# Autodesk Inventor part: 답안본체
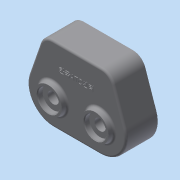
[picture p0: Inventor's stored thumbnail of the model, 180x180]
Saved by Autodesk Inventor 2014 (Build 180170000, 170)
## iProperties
Created: 2014-12
Part Number: 답안본체
Material: 일반
Document SubType Name: Modeling
Designer: user
Density: 1 g/cm^3
Appearance: 기본값
Author: user
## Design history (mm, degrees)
sketch "스케치1"
  geometry: L1 (-47, 0)-(47, 0); L2 (47, 0)-(66.565, -56.803); L3 (-47, 0)-(-66.565, -56.803); L4 (-32.527, -104.527)-(32.527, -104.527); L5 (-32.527, -68.527)-(0, -36); L6 (0, -36)-(32.527, -68.527); L7 (0, -36)-(0, -104.527); C1 r 24 at (0, -36); C2 r 24 at (-32.527, -68.527); C3 r 24 at (32.527, -68.527); A1 r 36 centre (32.527, -68.527) between (32.527, -104.527) and (66.565, -56.803); A2 r 36 centre (-32.527, -68.527) between (-66.565, -56.803) and (-32.527, -104.527); A3 r 46 centre (0, -36) between (32.527, -68.527) and (-32.527, -68.527); 2 further points
  constraints: 14 end point, 6 centre point, 6 point on circle, 5 coincident, 4 tangent, 2 midpoint, 1 horizontal, 1 horizontal alignment, 1 parallel, 1 perpendicular, 1 vertical alignment
  dimensions: "d0" = 36 radius of A2; "d1" = 94 distance of L1.start L1.end; "d2" = 36 distance from line of L6.end L4; "d5" = 92 diameter of A3; "d6" = 90 deg angle of L5 L6; "d7" = 48 diameter of C2; "d8" = 48 diameter of C3; "d9" = 48 diameter of C1; "d10" = 36 distance from line of L5.end L1
extrude "돌출1" new body sketch "스케치1" distance "d11" = 10; taper "d12" = 0 deg
node "작업 평면1"
sketch "스케치2"
  geometry: L1 (11.723, 10)-(-36, 10) reference; L2 (-20, 10)-(-18.766, 17); L3 (-18.766, 17)-(18.766, 17); L4 (68.527, 10)-(11.723, 10) reference; L5 (18.766, 17)-(20, 10); L6 (0, 0)-(0, 22.754); L7 (-36, 0)-(-36, 10) reference; L8 (0, 17)-(0, 10); L9 (0, 10)-(20, 10); 1 further point
  constraints: 12 end point, 5 point on line, 1 collinear, 1 midpoint, 1 parallel, 1 perpendicular
  dimensions: "d13" = 100 deg angle of L1 L2; "d14" = 100 deg angle of L4 L5; "d15" = 40 distance of L2.start L5.end; "d16" = 7 distance between parallel lines of L1 L3; "d17" = 36 distance between parallel lines of L7 L6
revolve "회전1" sketch "스케치2" stored, may be unused: angle "d18" = 90 deg
extrude "돌출2" join sketch "스케치1" distance "d19" = 34; taper "d20" = 0 deg
sketch "스케치3"
  geometry: C1 r 18.766 at (0, 0) reference; C2 r 18.766 at (-65.054, 0) reference; 3 further points
  constraints: 2 coincident
hole "구멍1" sketch "스케치3" at (0, 0), (-65.054, 0) diameter "d21" = 15.5; stored, may be unused: countersink angle "d25" = 90 deg, drill point angle "d27" = 0 deg; dims "d22" = 6, "d23" = 30, "d24" = 7, "d26" = 17
sketch "스케치4"
  geometry: L1 (66.565, -56.803)-(47, 0) reference; L2 (47, 0)-(-47, 0) reference; L3 (-47, 0)-(-66.565, -56.803) reference; L4 (-32.527, -104.527)-(32.527, -104.527) reference; L5 (-43.434, -5)-(43.434, -5); L6 (43.434, -5)-(61.837, -58.432); L7 (32.527, -99.527)-(-32.527, -99.527); L8 (-61.837, -58.432)-(-43.434, -5); A1 r 36 centre (-32.527, -68.527) between (-66.565, -56.803) and (-32.527, -104.527) reference; A2 r 36 centre (32.527, -68.527) between (32.527, -104.527) and (66.565, -56.803) reference; A3 r 31 centre (32.527, -68.527) between (32.527, -99.527) and (61.837, -58.432); A4 r 31 centre (-32.527, -68.527) between (-61.837, -58.432) and (-32.527, -99.527); 1 further point
  constraints: 8 end point, 4 point on circle, 2 centre point, 5 other
  dimensions: "d28" = 5 distance between parallel lines of L2 L5
extrude "돌출3" cut sketch "스케치4" distance "d29" = 23; taper "d30" = 0 deg
fillet "모깎기1" dims "d31" = 18
fillet "모깎기2" dims "d32" = 18
sketch "스케치5"
  geometry: L1 (-30.596, -5)-(30.596, -5) reference; L2 (-61.837, -58.432)-(-47.615, -17.138) reference; L3 (32.527, -99.527)-(-32.527, -99.527) reference; L4 (47.615, -17.138)-(61.837, -58.432) reference; A1 r 18 centre (30.596, -23) between (47.615, -17.138) and (30.596, -5) reference; A2 r 18 centre (-30.596, -23) between (-30.596, -5) and (-47.615, -17.138) reference; A3 r 31 centre (-32.527, -68.527) between (-61.837, -58.432) and (-32.527, -99.527) reference; A4 r 31 centre (32.527, -68.527) between (32.527, -99.527) and (61.837, -58.432) reference; 3 further points
  constraints: 2 coincident
hole "구멍2" sketch "스케치5" at (32.527, -68.527), (-32.527, -68.527) diameter "d33" = 35; stored, may be unused: countersink angle "d37" = 90 deg, drill point angle "d39" = 0 deg; dims "d34" = 6, "d35" = 30, "d36" = 7, "d38" = 11
sketch "스케치6"
  geometry: L1 (-30.596, -5)-(30.596, -5) reference; L2 (-61.837, -58.432)-(-47.615, -17.138) reference; L3 (32.527, -99.527)-(-32.527, -99.527) reference; L4 (47.615, -17.138)-(61.837, -58.432) reference; L5 (34.162, 0)-(-34.162, 0) reference; C1 r 17.5 at (32.527, -68.527) reference; C2 r 17.5 at (-32.527, -68.527) reference; A1 r 18 centre (30.596, -23) between (47.615, -17.138) and (30.596, -5) reference; A2 r 18 centre (-30.596, -23) between (-30.596, -5) and (-47.615, -17.138) reference; A3 r 31 centre (-32.527, -68.527) between (-61.837, -58.432) and (-32.527, -99.527) reference; A4 r 31 centre (32.527, -68.527) between (32.527, -99.527) and (61.837, -58.432) reference; A5 r 24 centre (-32.527, -68.527) between (-21.111, -47.416) and (-11.416, -57.111); A6 r 24 centre (32.527, -68.527) between (11.416, -57.111) and (21.111, -47.416); A7 r 24 centre (0, -36) between (21.111, -47.416) and (-21.111, -47.416); A8 r 24 centre (0, -36) between (-11.416, -57.111) and (11.416, -57.111); 2 further points
  constraints: 8 point on circle, 4 centre point, 2 coincident, 1 equal radius, 1 midpoint, 1 vertical alignment
  dimensions: "d40" = 48 diameter of A5; "d42" = 36 distance from line of A7.centre L5; "d43" = 24 radius of A7; "d44" = 24 radius of A8
extrude "돌출4" cut sketch "스케치6" distance "d45" = 11; taper "d46" = 0 deg
sketch "스케치7"
  geometry: C1 r 17.5 at (32.527, -68.527) reference; C2 r 17.5 at (-32.527, -68.527) reference; A1 r 24 centre (0, -36) between (21.111, -47.416) and (-21.111, -47.416) reference; A2 r 24 centre (-32.527, -68.527) between (-21.111, -47.416) and (-11.416, -57.111) reference; A3 r 24 centre (0, -36) between (-11.416, -57.111) and (11.416, -57.111) reference; A4 r 24 centre (32.527, -68.527) between (11.416, -57.111) and (21.111, -47.416) reference; 2 further points
  constraints: 1 coincident
hole "구멍3" sketch "스케치7" at (0, -36) diameter "d47" = 20; stored, may be unused: countersink angle "d51" = 90 deg, drill point angle "d53" = 0 deg; dims "d48" = 6, "d49" = 40, "d50" = 12, "d52" = 15
sketch "스케치8"
  geometry: L1 (-61.837, -58.432)-(-47.615, -17.138) reference; L2 (-30.596, -5)-(30.596, -5) reference; L3 (47.615, -17.138)-(61.837, -58.432) reference; L4 (32.527, -99.527)-(-32.527, -99.527) reference; L5 (-51.181, -12.138)-(-66.565, -56.803) reference; L6 (-32.527, -104.527)-(32.527, -104.527) reference; L7 (66.565, -56.803)-(51.181, -12.138) reference; L8 (34.162, 0)-(-34.162, 0) reference; L9 (47.615, -17.138)-(61.837, -58.432) reference; A1 r 18 centre (-30.596, -23) between (-30.596, -5) and (-47.615, -17.138) reference; A2 r 18 centre (30.596, -23) between (47.615, -17.138) and (30.596, -5) reference; A3 r 31 centre (32.527, -68.527) between (32.527, -99.527) and (61.837, -58.432) reference; A4 r 31 centre (-32.527, -68.527) between (-61.837, -58.432) and (-32.527, -99.527) reference; A5 r 18 centre (-34.162, -18) between (-34.162, 0) and (-51.181, -12.138) reference; A6 r 36 centre (-32.527, -68.527) between (-66.565, -56.803) and (-32.527, -104.527) reference; A7 r 36 centre (32.527, -68.527) between (32.527, -104.527) and (66.565, -56.803) reference; A8 r 18 centre (34.162, -18) between (51.181, -12.138) and (34.162, 0) reference; A9 r 8 centre (51.7, -29) between (49.095, -21.436) and (54.305, -36.564); 1 further point
  constraints: 3 point on line, 2 point on circle, 1 centre point
  dimensions: "d55" = 8 radius of A9; "d95" = 29 distance from line of A9.centre L8
extrude "돌출5" join sketch "스케치8" stored distance "d56" = 11; taper "d57" = 0 deg
sketch "스케치9"
  geometry: L1 (-51.181, -12.138)-(-66.565, -56.803) reference; L2 (-32.527, -104.527)-(32.527, -104.527) reference; L3 (66.565, -56.803)-(51.181, -12.138) reference; L4 (34.162, 0)-(-34.162, 0) reference; L5 (54.305, -36.564)-(61.837, -58.432) reference; L6 (32.527, -99.527)-(-32.527, -99.527) reference; L7 (-61.837, -58.432)-(-54.305, -36.564) reference; L8 (-49.095, -21.436)-(-47.615, -17.138) reference; L9 (-30.596, -5)-(30.596, -5) reference; L10 (47.615, -17.138)-(49.095, -21.436) reference; L11 (32.527, -99.527)-(-32.527, -99.527) reference; A1 r 18 centre (-34.162, -18) between (-34.162, 0) and (-51.181, -12.138) reference; A2 r 36 centre (-32.527, -68.527) between (-66.565, -56.803) and (-32.527, -104.527) reference; A3 r 36 centre (32.527, -68.527) between (32.527, -104.527) and (66.565, -56.803) reference; A4 r 18 centre (34.162, -18) between (51.181, -12.138) and (34.162, 0) reference; A5 r 8 centre (51.7, -29) between (49.095, -21.436) and (54.305, -36.564) reference; A6 r 31 centre (32.527, -68.527) between (32.527, -99.527) and (61.837, -58.432) reference; A7 r 31 centre (-32.527, -68.527) between (-61.837, -58.432) and (-32.527, -99.527) reference; A8 r 8 centre (-51.7, -29) between (-54.305, -36.564) and (-49.095, -21.436) reference; A9 r 18 centre (-30.596, -23) between (-30.596, -5) and (-47.615, -17.138) reference; A10 r 18 centre (30.596, -23) between (47.615, -17.138) and (30.596, -5) reference; A11 r 8 centre (0, -99.527) between (8, -99.527) and (-8, -99.527); 3 further points
  constraints: 3 point on circle, 2 midpoint, 2 point on line, 1 centre point, 1 vertical alignment
  dimensions: "d58" = 8 radius of A11
extrude "돌출6" join sketch "스케치9" stored distance "d59" = 11; taper "d60" = 0 deg
sketch "스케치10"
  geometry: L1 (-51.181, -12.138)-(-66.565, -56.803) reference; L2 (-32.527, -104.527)-(32.527, -104.527) reference; L3 (66.565, -56.803)-(51.181, -12.138) reference; L4 (34.162, 0)-(-34.162, 0) reference; L5 (-8, -99.527)-(-32.527, -99.527) reference; L6 (-61.837, -58.432)-(-54.305, -36.564) reference; L7 (-49.095, -21.436)-(-47.615, -17.138) reference; L8 (-30.596, -5)-(30.596, -5) reference; L9 (47.615, -17.138)-(49.095, -21.436) reference; L10 (54.305, -36.564)-(61.837, -58.432) reference; L11 (32.527, -99.527)-(8, -99.527) reference; A1 r 18 centre (-34.162, -18) between (-34.162, 0) and (-51.181, -12.138) reference; A2 r 36 centre (-32.527, -68.527) between (-66.565, -56.803) and (-32.527, -104.527) reference; A3 r 36 centre (32.527, -68.527) between (32.527, -104.527) and (66.565, -56.803) reference; A4 r 18 centre (34.162, -18) between (51.181, -12.138) and (34.162, 0) reference; A5 r 8 centre (0, -99.527) between (8, -99.527) and (-8, -99.527) reference; A6 r 31 centre (-32.527, -68.527) between (-61.837, -58.432) and (-32.527, -99.527) reference; A7 r 8 centre (-51.7, -29) between (-54.305, -36.564) and (-49.095, -21.436) reference; A8 r 18 centre (-30.596, -23) between (-30.596, -5) and (-47.615, -17.138) reference; A9 r 18 centre (30.596, -23) between (47.615, -17.138) and (30.596, -5) reference; A10 r 8 centre (51.7, -29) between (49.095, -21.436) and (54.305, -36.564) reference; A11 r 31 centre (32.527, -68.527) between (32.527, -99.527) and (61.837, -58.432) reference; 4 further points
  constraints: 3 coincident
hole "구멍4" sketch "스케치10" at (-51.7, -29), (51.7, -29), (0, -99.527) diameter "d61" = 4.134; stored, may be unused: countersink angle "d65" = 90 deg, drill point angle "d67" = 118 deg; dims "d62" = 20, "d63" = 40, "d64" = 12, "d66" = 23
fillet "모깎기3" dims "d68" = 3
fillet "모깎기4" dims "d69" = 3
fillet "모깎기5" dims "d70" = 3
fillet "모깎기6" dims "d71" = 3
fillet "모깎기7" dims "d72" = 3
fillet "모깎기8" dims "d73" = 0.3
fillet "모깎기9" dims "d74" = 3
fillet "모깎기10" dims "d75" = 0.3
fillet "모깎기11" dims "d76" = 0.1
chamfer "모따기1" distance "d77" = 1; stored, may be unused: second distance "d78" = 2, angle "d79" = 45 deg
chamfer "모따기2" distance "d80" = 1; stored, may be unused: second distance "d81" = 2, angle "d82" = 45 deg
chamfer "모따기3" distance "d83" = 1; stored, may be unused: second distance "d84" = 2, angle "d85" = 45 deg
chamfer "모따기4" distance "d86" = 1; stored, may be unused: second distance "d87" = 2, angle "d88" = 45 deg
chamfer "모따기5" distance "d89" = 1; stored, may be unused: second distance "d90" = 2, angle "d91" = 45 deg
sketch "스케치11"
  geometry: 2 further points
  constraints: 1 vertical alignment, 1 other
  dimensions: "d92" = 30 distance of point (0, -30) point (0, 0)
feature "엠보싱1" sketch "스케치11" dims "d0" = 36, "d1" = 94, "d2" = 36, "d5" = 92, "d6" = 90 deg, "d7" = 48, "d8" = 48, "d9" = 48, "d10" = 36, "d13" = 100 deg, "d14" = 100 deg, "d15" = 40, "d16" = 7, "d17" = 36, "d93" = 1, "d94" = 0
fillet "모깎기12" dims "d96" = 3
node "솔리드1"
mirror "대칭1"
mirror "대칭2"
node "투영된 루프1"
node "투영된 루프2"
node "투영된 루프3"
node "투영된 루프4"
node "투영된 루프5"
node "투영된 루프6"
node "투영된 루프7"
node "투영된 루프8"
node "투영된 루프9"
other parameters: "d41" = 48
